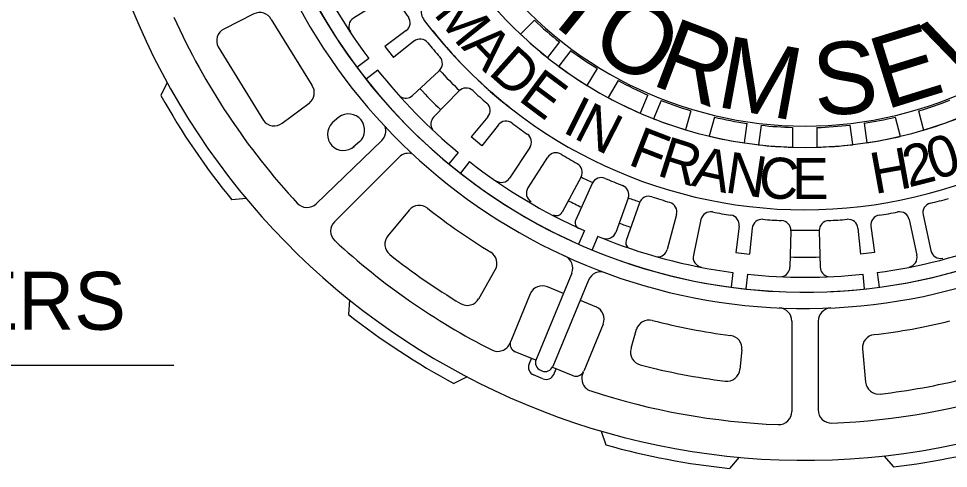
# Model space of a CAD drawing. Extents: x -7.1 to 10, y -5 to 6.
# Drawn here: x -2.543 to -1.07, y -0.447 to 0.265 of the extents above; entities that cross this region are included whole.
import ezdxf

# ---------------------------------------------------------------- set-up
doc = ezdxf.new("R2010")
doc.units = 0
doc.layers.add('Level 1', color=7, linetype='Continuous')
doc.layers.add('Level 12', color=7, linetype='Continuous')

# ---------------------------------------------------------------- blocks, each defined once
blk = doc.blocks.new('CRAN')
at = {"layer": 'Level 1'}
for p, q in [((-3.652, 6.599), (-1.391, 7.083)), ((-3.232, 4.178), (-1.568, 4.4)), ((-1.568, 4.4), (-1.47, 3.52)), ((-3.114, 3.352), (-1.47, 3.52)), ((-2.949, 0.9), (-0.638, 0.965)), ((-2.949, -0.892), (-0.638, -0.957)), ((-3.114, -3.345), (-1.471, -3.52)), ((-1.568, -4.392), (-1.47, -3.512)), ((-3.232, -4.17), (-1.568, -4.392)), ((-3.652, -6.592), (-1.391, -7.076))]:
    blk.add_line(p, q, dxfattribs=at)
for centre, radius, start, end in [((-1.26, 6.472), 0.625, 11.01435, 102.07218), ((-3.521, 5.988), 0.625, 102.07218, 190.93682), ((-34.491, 0.004), 30.918, 8.74094, 10.93682), ((-3.315, 4.797), 0.625, 188.74094, 277.60558), ((-3.048, 2.731), 0.625, 96.07758, 184.94222), ((-34.473, 0.013), 30.918, 2.74634, 4.94222), ((-2.967, 1.524), 0.625, 182.74634, 271.61098), ((-0.656, 1.589), 0.625, 271.61098, 348.82418), ((-2.967, -1.517), 0.625, 88.38902, 177.25366), ((-0.656, -1.582), 0.625, 11.17582, 88.38902), ((-34.473, -0.006), 30.918, 355.05778, 357.25366), ((-3.048, -2.723), 0.625, 175.05778, 263.92242), ((-34.491, 0.004), 30.918, 349.06318, 351.25906), ((-3.315, -4.79), 0.625, 82.39442, 171.25906), ((-3.521, -5.981), 0.625, 169.06318, 257.92782), ((-1.26, -6.464), 0.625, 257.92782, 348.98565)]:
    blk.add_arc(centre, radius, start, end, dxfattribs=at)

msp = doc.modelspace()

# ---------------------------------------------------------------- linework, layer by layer
at = {"layer": 'Level 1'}
for p, q in [((-2.1701, 0.2723), (-2.2175, 0.2483)), ((-2.1423, 0.2635), (-2.078, 0.1595)), ((-1.7256, 0.2622), (-1.7477, 0.2402)), ((-1.6859, 0.2279), (-1.7051, 0.2032)), ((-2.2265, 0.22), (-2.1547, 0.1037)), ((-1.668, 0.2142), (-1.687, 0.1894)), ((-1.9879, 0.2017), (-2.0067, 0.1877)), ((-1.9739, 0.1834), (-1.9923, 0.1689)), ((-1.6265, 0.1861), (-1.6424, 0.1592)), ((-2.3071, 0.1639), (-2.3173, 0.143)), ((-1.5932, 0.1668), (-1.6089, 0.1398)), ((-1.546, 0.144), (-1.5581, 0.1151)), ((-1.5251, 0.1353), (-1.5371, 0.1064)), ((-2.0826, 0.1307), (-2.1253, 0.099)), ((-1.4778, 0.1189), (-1.4862, 0.0888)), ((-1.1173, 0.1187), (-1.1093, 0.0884)), ((-2.0353, 0.1088), (-2.0458, 0.0997)), ((-1.4407, 0.1089), (-1.4488, 0.0788)), ((-1.1545, 0.1087), (-1.1466, 0.0785)), ((-1.3892, 0.0991), (-1.3934, 0.0681)), ((-1.3667, 0.0961), (-1.3708, 0.0651)), ((-1.3168, 0.0925), (-1.3171, 0.0613)), ((-1.2783, 0.0925), (-1.2784, 0.0613)), ((-1.2261, 0.0963), (-1.2221, 0.0653)), ((-1.2036, 0.0993), (-1.1995, 0.0683)), ((-1.9673, 0.072), (-2.0714, -0.0283)), ((-2.002, 0.0703), (-2.0125, 0.0612)), ((-1.94, 0.0455), (-2.0424, -0.0568)), ((-1.8463, 0.0529), (-1.8613, 0.0348)), ((-1.7047, 0.0454), (-1.736, -0.0032)), ((-1.8284, 0.0385), (-1.8429, 0.02)), ((-1.6518, 0.0142), (-1.6818, -0.0416)), ((-1.634, 0.0039), (-1.6603, -0.0537)), ((-2.1817, -0.0201), (-2.205, -0.0219)), ((-1.5772, -0.0193), (-1.5969, -0.0736)), ((-1.5593, -0.0269), (-1.5805, -0.0866)), ((-1.9241, -0.0383), (-1.9578, -0.079)), ((-1.5006, -0.0451), (-1.5156, -0.1009)), ((-1.1102, -0.046), (-1.098, -0.1025)), ((-1.6466, -0.0707), (-1.6561, -0.0921)), ((-1.6255, -0.0797), (-1.6344, -0.1014)), ((-1.8139, -0.1788), (-1.7876, -0.1332)), ((-1.6664, -0.1381), (-1.7231, -0.275)), ((-1.4112, -0.1372), (-1.4143, -0.1604)), ((-1.3884, -0.1399), (-1.3909, -0.1632)), ((-1.2058, -0.1399), (-1.2034, -0.1632)), ((-1.183, -0.1372), (-1.1799, -0.1604)), ((-1.6797, -0.1703), (-1.705, -0.1598)), ((-1.64, -0.1491), (-1.6967, -0.286)), ((-1.7322, -0.1711), (-1.7631, -0.2457)), ((-2.0184, -0.1805), (-2.0199, -0.2036)), ((-1.6533, -0.1812), (-1.628, -0.1917)), ((-1.6167, -0.2189), (-1.6476, -0.2935)), ((-1.3179, -0.2141), (-1.3179, -0.3573)), ((-1.2763, -0.2141), (-1.2763, -0.3549)), ((-1.5643, -0.2276), (-1.5728, -0.2576)), ((-1.7631, -0.2457), (-1.7646, -0.2492)), ((-1.7236, -0.2761), (-1.7561, -0.2627)), ((-1.3971, -0.2597), (-1.4003, -0.2907)), ((-1.2061, -0.2582), (-1.2012, -0.3109)), ((-1.7342, -0.2822), (-1.7305, -0.2732)), ((-1.7149, -0.2925), (-1.7149, -0.2925)), ((-1.6971, -0.2871), (-1.6647, -0.3005)), ((-1.6951, -0.2985), (-1.6914, -0.2895)), ((-1.8322, -0.3025), (-1.8531, -0.3131)), ((-1.7121, -0.3055), (-1.7272, -0.2993)), ((-1.6483, -0.2949), (-1.6492, -0.297)), ((-1.62, -0.3882), (-1.6125, -0.4101)), ((-1.4013, -0.4297), (-1.4165, -0.4474)), ((-1.1724, -0.4276), (-1.157, -0.445))]:
    msp.add_line(p, q, dxfattribs=at)
for centre, radius, start, end in [((-1.2973, 0.7173), 1.1516, 195.0717, 189.1227), ((-1.2971, 0.7172), 0.8854, 184.6051, 245.3048), ((-1.2971, 0.7172), 0.8854, 184.6051, 354.3326), ((-1.2971, 0.7172), 0.8854, 272.6352, 354.3326), ((-1.2971, 0.7172), 0.9115, 188.0305, 347.6848), ((-1.2971, 0.7172), 0.862, 202.6056, 216.7344), ((-1.2971, 0.7172), 0.6224, 216.9847, 323.0153), ((-1.2971, 0.7172), 0.6562, 217.1874, 322.8126), ((-1.8793, 0.2778), 0.026, 125, 217.0904), ((-1.2958, 0.7194), 1.0983, 204.3143, 222.8654), ((-2.1607, 0.2537), 0.0208, 28.0611, 116.8565), ((-1.2973, 0.7178), 0.7557, 217.0904, 322.9239), ((-1.2971, 0.7172), 0.625, 226.7203, 231.5279), ((-2.2081, 0.2297), 0.0208, 116.8565, 207.9663), ((-1.2971, 0.7174), 0.7552, 218.3392, 223.6005), ((-1.2971, 0.7172), 0.6563, 226.6317, 231.5646), ((-1.2971, 0.7172), 0.625, 233.6043, 238.1939), ((-1.2971, 0.7172), 0.862, 218.262, 230.418), ((-1.2971, 0.7172), 0.7875, 222.7158, 225.9774), ((-1.2971, 0.7172), 0.6563, 233.552, 238.2544), ((-1.2973, 0.7175), 0.7552, 226.4152, 231.6765), ((-1.2971, 0.7172), 0.625, 241.7203, 246.5279), ((-2.095, 0.1474), 0.0208, 306.5465, 35.3378), ((-1.2971, 0.7172), 0.8301, 222.7192, 225.9733), ((-1.2972, 0.7166), 1.1703, 209.3462, 219.1251), ((-1.2971, 0.7172), 0.6563, 241.6317, 246.5646), ((-1.2971, 0.7172), 0.625, 248.6043, 253.1939), ((-1.2971, 0.7172), 0.625, 286.7203, 291.5279), ((-2.1377, 0.1158), 0.0208, 215.392, 306.5465), ((-2.02, 0.0884), 0.0255, 311.5699, 126.9738), ((-1.2971, 0.7172), 0.6563, 248.552, 253.2544), ((-1.2971, 0.7172), 0.625, 256.7203, 261.5279), ((-1.2971, 0.7172), 0.625, 278.6043, 283.1939), ((-1.2971, 0.7172), 0.6563, 286.6317, 291.5646), ((-2.0278, 0.0816), 0.0255, 134.687, 311.5622), ((-1.9817, 0.087), 0.0208, 313.9401, 20.0195), ((-1.2971, 0.7172), 0.625, 263.6043, 268.1939), ((-1.2971, 0.7172), 0.625, 271.7203, 276.5279), ((-1.2971, 0.7172), 0.6563, 256.6317, 261.5646), ((-1.2971, 0.7172), 0.6563, 278.552, 283.2544), ((-1.2971, 0.7172), 0.6563, 263.552, 268.2544), ((-1.2971, 0.7172), 0.6563, 271.6317, 276.5646), ((-1.9253, 0.0308), 0.0208, 71.0549, 135), ((-1.6915, 0.0369), 0.0156, 58.3474, 147.2121), ((-1.2777, 0.7082), 0.7729, 238.3474, 240.5433), ((-1.2971, 0.7172), 0.862, 231.9456, 246.078), ((-1.6655, 0.0216), 0.0156, 331.6787, 60.5433), ((-1.2971, 0.7172), 0.7875, 243.2323, 244.7184), ((-1.6198, -0.0025), 0.0156, 66.704, 155.5686), ((-1.308, 0.7218), 0.7729, 246.704, 248.8998), ((-1.5918, -0.0139), 0.0156, 340.0352, 68.8998), ((-1.7228, -0.0116), 0.0156, 147.2121, 238.2699), ((-2.0859, -0.0133), 0.0208, 222.8438, 313.9401), ((-1.2971, 0.7172), 0.8301, 243.1524, 244.7577), ((-1.2971, 0.7172), 0.7875, 249.1803, 250.5909), ((-1.5446, -0.0321), 0.0156, 71.6109, 160.4756), ((-1.2958, 0.7162), 0.7729, 251.6109, 253.8068), ((-1.5157, -0.0411), 0.0156, 344.9422, 73.8068), ((-1.095, -0.0427), 0.0156, 103.3474, 192.2121), ((-1.277, 0.7246), 0.7729, 283.3474, 285.5433), ((-1.908, -0.0516), 0.0208, 51.5447, 140.3232), ((-1.2958, 0.7193), 0.9635, 231.5447, 238.807), ((-1.691, -0.0367), 0.0104, 240.9692, 331.6787), ((-2.0276, -0.0715), 0.0208, 135, 227.2195), ((-1.6508, -0.058), 0.0104, 155.5686, 246.2781), ((-1.2971, 0.7172), 0.8301, 249.2248, 250.5852), ((-1.6116, -0.0683), 0.0156, 248.9774, 340.0352), ((-1.2971, 0.7172), 0.7875, 268.3758, 271.6374), ((-1.2958, 0.7194), 1.0983, 227.2195, 243.0661), ((-1.9418, -0.0923), 0.0208, 140.3232, 231.5594), ((-1.2971, 0.7172), 0.862, 247.6056, 262.3944), ((-1.5706, -0.0901), 0.0104, 160.4756, 228.3766), ((-1.2971, 0.7172), 0.862, 277.6056, 291.078), ((-1.5307, -0.0969), 0.0156, 270.2442, 344.9422), ((-1.0827, -0.0992), 0.0156, 192.2121, 283.2699), ((-1.299, 0.7176), 1.0548, 231.5594, 238.9682), ((-1.8057, -0.1228), 0.0208, 330.0206, 58.807), ((-1.6857, -0.1302), 0.0208, 337.5, 65.3048), ((-1.2967, 0.7161), 0.8845, 249.7003, 267.3328), ((-1.2971, 0.7172), 0.8301, 268.3792, 271.6333), ((-1.6207, -0.157), 0.0208, 69.7003, 157.5), ((-1.2971, 0.7172), 0.862, 263.922, 276.078), ((-1.713, -0.179), 0.0208, 67.5, 157.5), ((-1.832, -0.1684), 0.0208, 238.9682, 330.0206), ((-1.2969, 0.7166), 1.1703, 231.8462, 241.6251), ((-1.636, -0.2109), 0.0208, 337.5, 67.5), ((-1.3388, -0.2141), 0.0208, 0, 87.3648), ((-1.2554, -0.2141), 0.0208, 92.6352, 180), ((-1.5442, -0.2333), 0.0208, 75.3841, 164.1622), ((-1.2958, 0.7193), 0.9635, 255.3841, 262.8801), ((-1.2976, 0.7217), 0.9635, 276.5447, 283.807), ((-1.1854, -0.2563), 0.0208, 96.5447, 185.3232), ((-1.7839, -0.2413), 0.0208, 243.0661, 337.5), ((-1.7511, -0.2506), 0.013, 157.5, 247.5), ((-1.4178, -0.2575), 0.0208, 354.1639, 82.8801), ((-1.5527, -0.2633), 0.0208, 164.1622, 255.3463), ((-1.7111, -0.28), 0.013, 157.5, 247.4327), ((-1.7222, -0.2872), 0.013, 157.5, 247.5), ((-1.2958, 0.7193), 1.0951, 247.4327, 247.5706), ((-1.7087, -0.281), 0.013, 247.5706, 337.5), ((-1.6597, -0.2885), 0.013, 247.5, 337.5), ((-1.2958, 0.7193), 1.0365, 255.3463, 262.9191), ((-1.421, -0.2886), 0.0208, 262.9191, 354.1639), ((-1.7071, -0.2935), 0.013, 247.5, 337.5), ((-1.63, -0.305), 0.0208, 157.5, 251.9323), ((-1.2986, 0.7183), 1.0548, 276.5594, 283.9682), ((-1.2976, 0.7218), 1.0983, 272.2423, 288.0661), ((-1.1805, -0.3089), 0.0208, 185.3232, 276.5594), ((-1.2958, 0.7194), 1.0983, 251.9323, 267.7134), ((-1.3388, -0.3573), 0.0208, 267.7134, 0), ((-1.2554, -0.3549), 0.0208, 180, 272.2423), ((-1.2967, 0.7167), 1.1703, 254.3462, 264.1251), ((-1.2965, 0.7169), 1.1703, 276.8462, 286.6251)]:
    msp.add_arc(centre, radius, start, end, dxfattribs=at)
at = {"layer": 'Level 12'}
msp.add_line((-3.6091, -0.2838), (-2.2967, -0.2838), dxfattribs=at)

# ---------------------------------------------------------------- block references
at = {"layer": 'Level 1', "xscale": 0.025}
for p, yscale, rotation in [((-1.9136, 0.1148), 0.024999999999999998, -135.66), ((-1.2971, -0.1447), 0.025000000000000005, -90.00000000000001)]:
    msp.add_blockref('CRAN', p, dxfattribs=dict(at, yscale=yscale, rotation=rotation))

# ---------------------------------------------------------------- texts
at = {"layer": 'Level 1'}
for s, height, rotation, p in [('T', 0.1144, 321.156, (-1.7178, 0.2727)), ('W', 0.1144, 29.0041, (-1.0617, 0.1527)), ('M', 0.0651, 308.7803, (-1.8866, 0.2721)), ('O', 0.1144, 329.108, (-1.6428, 0.2156)), ('R', 0.1144, 339.2395, (-1.5434, 0.1612)), ('E', 0.1144, 17.2263, (-1.1699, 0.1201)), ('A', 0.0651, 313.6923, (-1.8425, 0.2195)), ('M', 0.1144, 349.6504, (-1.4402, 0.126)), ('D', 0.0651, 318.2167, (-1.8004, 0.1781)), ('S', 0.1144, 4.56, (-1.2802, 0.1101)), ('E', 0.0651, 323.2871, (-1.7531, 0.1366)), ('I', 0.0651, 333.3702, (-1.6832, 0.086)), ('N', 0.0651, 332.9221, (-1.6654, 0.0764)), ('F', 0.0651, 338.7445, (-1.5794, 0.0345)), ('R', 0.0651, 342.4543, (-1.5337, 0.0172)), ('0', 0.0651, 17.3354, (-1.0927, 0.0086)), ('A', 0.0651, 347.5495, (-1.4789, 0.0008)), ('H', 0.0651, 10.2946, (-1.1871, -0.0132)), ('2', 0.0651, 14.1438, (-1.1331, -0.0027)), ('N', 0.0651, 351.4595, (-1.4256, -0.0099)), ('C', 0.0651, 355.9795, (-1.372, -0.0181)), ('E', 0.0651, 359.8895, (-1.3176, -0.0209))]:
    msp.add_text(s, height=height, rotation=rotation, dxfattribs=at).set_placement(p)
at = {"layer": 'Level 12'}
msp.add_text('MANHOLE COVERS', height=0.091813, dxfattribs=at).set_placement((-3.5324, -0.2278))

doc.saveas('drawing.dxf')
